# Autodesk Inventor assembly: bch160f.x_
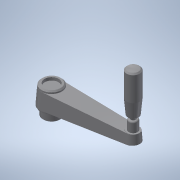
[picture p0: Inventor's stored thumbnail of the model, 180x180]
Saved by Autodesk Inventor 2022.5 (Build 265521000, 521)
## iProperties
Part Number: bch160f.x_
Material: 一般
Document SubType Name: Assembly
Designer: ImaoCorp
Sending System: SOLIDWORKS 2017-2017317
MC: AMD64
MC_MODEL: Intel64 Family 6 Model 60 Stepping 3, GenuineIntel
OS: Windows_NT
FRU: Parasolid Version 29.0, build 201,  4-17-2017
FORMAT: text
GUISE: transmit
KEY: bch160f
FILE: bch160f.x_t
DATE: Fri Mar 15 10:33:56 2019
Author: ImaoCorp
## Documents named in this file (3)
- X:\14_SW2022-Inv2022\00_全2023-1023新製品(TCC)まで\b\bch160f\BCH160F.iam
- X:\14_SW2022-Inv2022\00_全2023-1023新製品(TCC)まで\b\bch160f\bch160f_01.ipt
- X:\14_SW2022-Inv2022\00_全2023-1023新製品(TCC)まで\b\bch160f\bch160f_02.ipt
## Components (2 placed, 2 different names)
1. bch160f_01
2. bch160f_02
